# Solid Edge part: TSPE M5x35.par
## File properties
Title: 1320201890
Subject: Vite TSPEI M5x35
Author: g_deluca
Template: RBuno.par
Last saved by: g_deluca
Revision: 15
Application: Solid Edge
Material: Classe 10.9
Tipo di contenuto documento: 0
Company: EFFEBI S.p.A.
Codice: Codice
Indice rev.: Rev.
Data rev.: Data rev.
Firma rev.: Firma rev.
Descrizione rev.: Descrizione rev.
Densità: 7860.000 kg/m^3
Precisione: 0.99
Document Number: UNI 5933
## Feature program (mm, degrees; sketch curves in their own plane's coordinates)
sketch for "unnamed RevolvedProtrusion 1" plane through (0, 0, 0) normal (0, -1, 0) x-axis (1, 0, 0)
revolve "unnamed RevolvedProtrusion 1" add finite 360 deg
sketch for "unnamed Protrusion 1" plane through (0, 0, 2.8) normal (0, 0, 1) x-axis (1, 0, 0)
  circle centre (0, 0) radius 2.5
extrude "unnamed Protrusion 1" add finite 35 along -normal
sketch for "ExtrudedCutout_1" plane through (0, 0, 2.8) normal (0, 0, 1) x-axis (1, 0, 0)
  line (-1.5, 0.866) -> (-1.5, -0.866)
  line (0, -1.7321) -> (-1.5, -0.866)
  line (0, -1.7321) -> (1.5, -0.866)
  line (1.5, 0.866) -> (1.5, -0.866)
  line (1.5, 0.866) -> (0, 1.7321)
  line (-1.5, 0.866) -> (0, 1.7321)
extrude "ExtrudedCutout_1" cut finite 3 along -normal
thread "unnamed Thread 1"
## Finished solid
Body 1: solid body, 12 faces, 22 edges, 12 vertices.
  Faces by surface: plane 9, cylinder 2, cone 1
  Edges by curve: line 18, circle 4
Bounding box of the edges (mm): 10.000 x 10.000 x 35.000, from (-5, -5, -32.2) to (5, 5, 2.8).
Cylindrical faces by radius (mm): R2.5 x1, R5 x1
Conical faces (half-angle, radius in mm at the cone's reference point): 45 deg R2.5 x1
Planar faces by outward normal: +x 1, +z 2, -x 1, -z 1, oblique 4
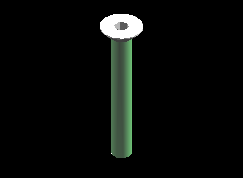
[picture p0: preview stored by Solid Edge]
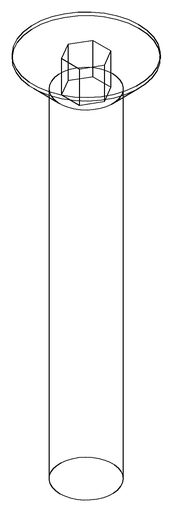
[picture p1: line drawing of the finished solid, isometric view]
